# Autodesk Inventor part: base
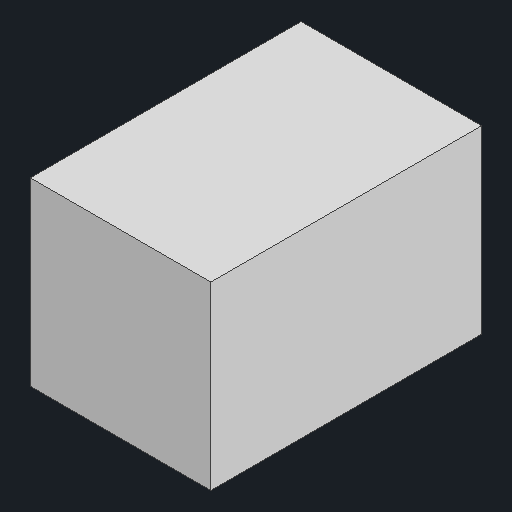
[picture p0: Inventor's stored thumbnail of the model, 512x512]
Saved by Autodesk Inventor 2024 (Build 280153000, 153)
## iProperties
Created: 2023-09
Part Number: base
Material: Generic
Document SubType Name: Modeling
Designer: mammothbane
Density: 1 g/cm^3
Appearance: Default
Author: mammothbane
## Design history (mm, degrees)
derived "joystick_block.ipt"
feature "base::joystick_block.ipt" dims "d0" = 10
tag "TaggingFeature1"
node "base"
